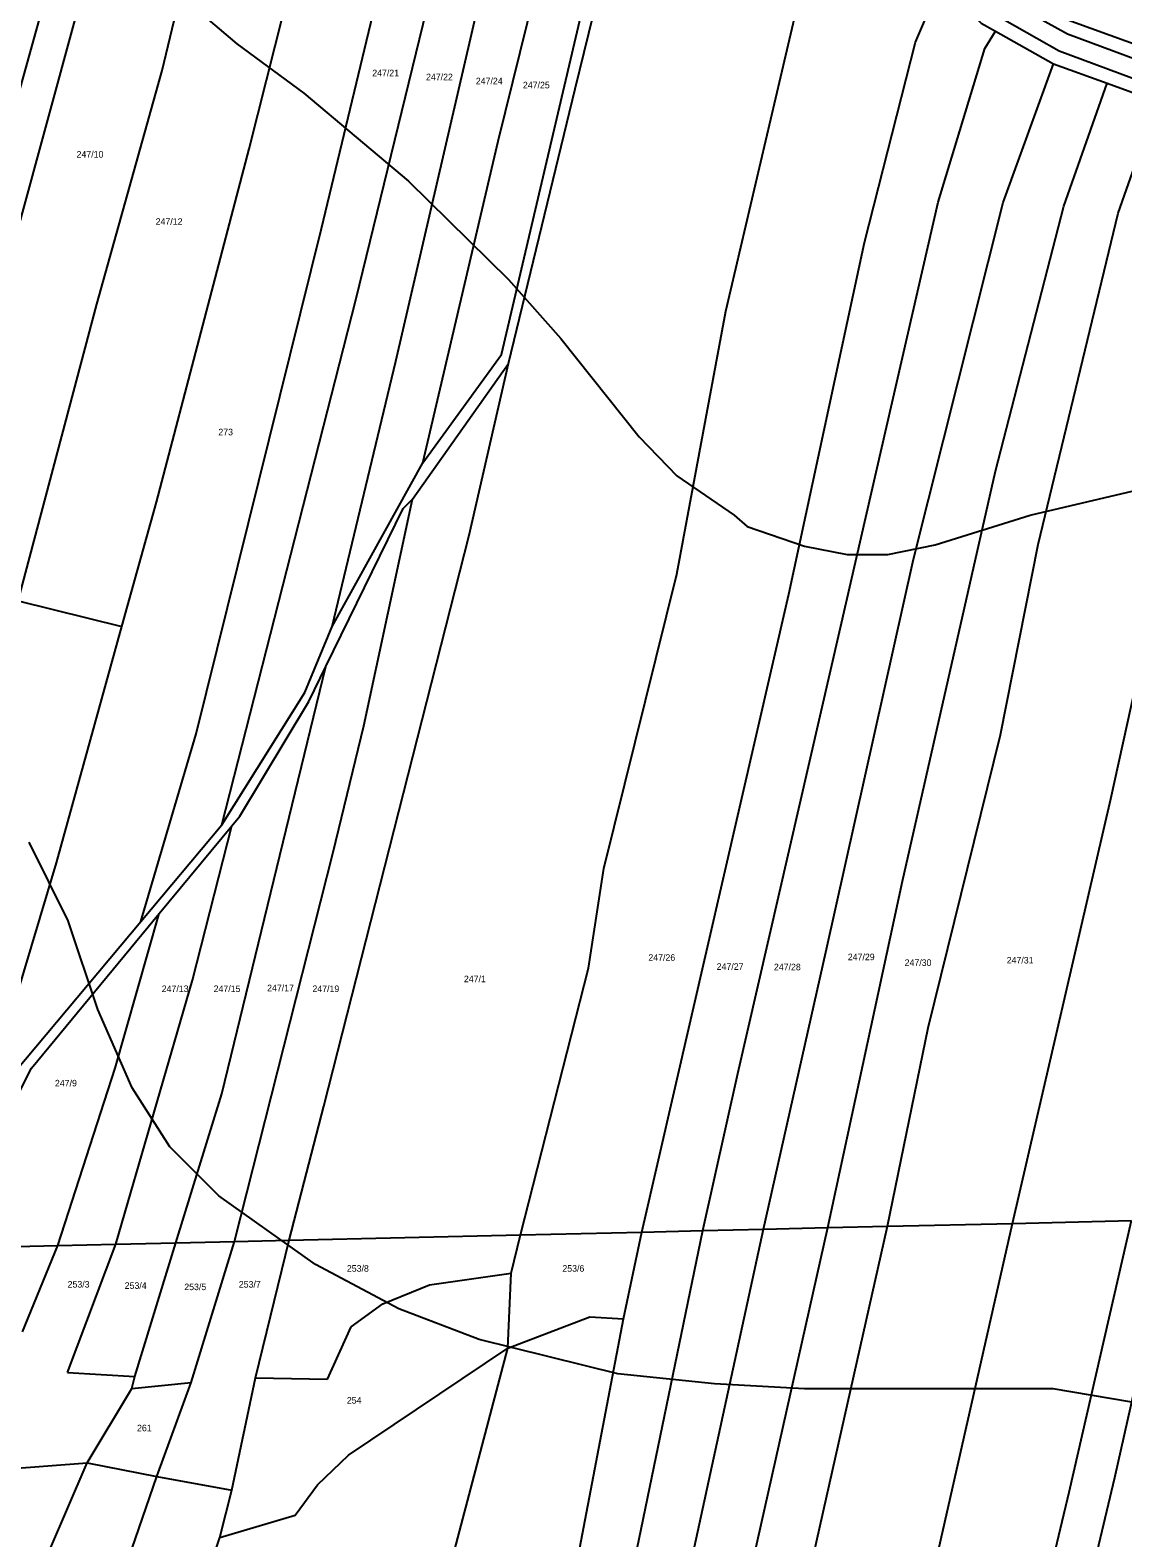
# Model space of a CAD drawing. Extents: x -743888 to -742027, y -1128394 to -1126768.
# Drawn here: x -743261.6 to -742978.3, y -1128180.2 to -1127789.2 of the extents above; entities that cross this region are included whole.
import ezdxf

# ---------------------------------------------------------------- set-up
doc = ezdxf.new("R2010")
doc.units = 0
for name, color, linetype in [('Vrstva 1', 7, 'Continuous'), ('Vrstva 18', 7, 'Continuous'), ('Vrstva 4', 7, 'Continuous'), ('Vrstva 52', 7, 'Continuous'), ('Vrstva 6', 7, 'Continuous')]:
    doc.layers.add(name, color=color, linetype=linetype)

msp = doc.modelspace()

# ---------------------------------------------------------------- linework, layer by layer
at = {"layer": 'Vrstva 1'}
for points in [[(-743015.05, -1127787.39), (-743011.33, -1127789.48)], [(-742991.64, -1127786.82), (-742967.48, -1127795.61)], [(-743011.33, -1127789.48), (-742996.28, -1127797.93)], [(-742996.28, -1127797.93), (-742982.41, -1127802.98)], [(-742982.41, -1127802.98), (-742971.25, -1127807.04)], [(-743134.48, -1128101.6), (-743103, -1128100.87)], [(-743103, -1128100.87), (-743087.22, -1128100.5)], [(-743087.22, -1128100.5), (-743071.48, -1128100.13)], [(-743071.48, -1128100.13), (-743054.77, -1128099.74)], [(-743054.77, -1128099.74), (-743039.34, -1128099.38)], [(-743039.34, -1128099.38), (-743006.9, -1128098.63)], [(-743006.9, -1128098.63), (-742976.11, -1128097.91)], [(-743283.67, -1128105.07), (-743254.5, -1128104.39)], [(-743254.5, -1128104.39), (-743239.47, -1128104.04)], [(-743239.47, -1128104.04), (-743223.91, -1128103.68)], [(-743223.91, -1128103.68), (-743208.7, -1128103.33)], [(-743208.7, -1128103.33), (-743194.5, -1128103)], [(-743194.5, -1128103), (-743134.48, -1128101.6)]]:
    msp.add_lwpolyline(points, dxfattribs=at)
at = {"layer": 'Vrstva 4'}
for points in [[(-743008.52, -1127781.37), (-742992.69, -1127790.12)], [(-743012.17, -1127784.72), (-742994.83, -1127794.53)], [(-742992.69, -1127790.12), (-742968.49, -1127799.16)], [(-742994.83, -1127794.53), (-742969.96, -1127803.78)]]:
    msp.add_lwpolyline(points, dxfattribs=at)
at = {"layer": 'Vrstva 52'}
for points in [[(-743053.67, -1127722.32), (-743053.72, -1127722.94), (-743049.21, -1127739.41), (-743048.14, -1127743.3), (-743040.35, -1127758.3), (-743030.5, -1127771.33), (-743025.38, -1127776.65), (-743015.05, -1127787.39), (-743011.33, -1127789.48), (-742996.28, -1127797.93), (-742982.41, -1127802.98), (-742971.25, -1127807.04), (-742969.31, -1127807.66), (-742941.27, -1127816.58), (-742913.36, -1127825.45), (-742905.98, -1127827.8), (-742901.58, -1127829.29), (-742887.63, -1127833.99), (-742883.39, -1127836.13), (-742870.31, -1127842.73), (-742866.75, -1127845.26), (-742862.04, -1127848.59)], [(-743039.23, -1127734.18), (-743037.36, -1127739.74), (-743036.47, -1127741.45), (-743030.16, -1127753.57), (-743021.89, -1127765.25), (-743006.65, -1127779.24), (-742997.92, -1127784.13), (-742991.64, -1127786.82), (-742967.48, -1127795.61), (-742902.77, -1127815.89), (-742889.66, -1127821.18), (-742882.56, -1127824.07), (-742864.61, -1127832.85), (-742855.17, -1127839.32)], [(-743237.75, -1127767.38), (-743208.06, -1127792.75), (-743190.69, -1127805.5), (-743163.5, -1127828.38), (-743137.63, -1127853.88), (-743124.06, -1127869.13), (-743103.69, -1127894.63), (-743093.94, -1127904.75), (-743079.13, -1127915), (-743075.69, -1127917.88), (-743060.88, -1127923), (-743049.81, -1127925.13), (-743039.25, -1127925.13), (-743026.94, -1127922.63), (-743002.31, -1127915), (-742975.56, -1127908.63)], [(-742971.38, -1128145.75), (-742996.38, -1128141.5), (-743060.88, -1128141.5), (-743084.19, -1128140.25), (-743109.25, -1128137.63), (-743145.25, -1128128.75), (-743166.06, -1128120.75), (-743187.69, -1128109.25), (-743212.75, -1128091.5), (-743225.44, -1128078.75), (-743235.19, -1128063.5), (-743244.13, -1128043.13), (-743251.75, -1128020.13), (-743261.94, -1127999.75)]]:
    msp.add_lwpolyline(points, dxfattribs=at)
at = {"layer": 'Vrstva 6'}
for points in [[(-743227.42, -1127799.64), (-743205.44, -1127708.1)], [(-743186.13, -1127840.64), (-743155.72, -1127714.23)], [(-743140.31, -1127817.95), (-743115.61, -1127717.91)], [(-743166.85, -1127875.07), (-743131.1, -1127720.81)], [(-743120.32, -1127804.45), (-743100.45, -1127723.29)], [(-743204.89, -1127820), (-743186.75, -1127748.28)], [(-743300.05, -1127932.95), (-743249, -1127749.54)], [(-743177.21, -1127859.16), (-743152.4, -1127757.44)], [(-743139.42, -1127873.34), (-743112.61, -1127758.91)], [(-743081.3, -1127862.06), (-743057.88, -1127762.39)], [(-743032.09, -1127792.31), (-743025.38, -1127776.65)], [(-743287.33, -1127923.2), (-743249.75, -1127785.46)], [(-743045.29, -1127844.24), (-743032.09, -1127792.31)], [(-743014.07, -1127793.96), (-743011.33, -1127789.48)], [(-743026.17, -1127833.83), (-743014.07, -1127793.96)], [(-743244.37, -1127860.25), (-743227.42, -1127799.64)], [(-743009.32, -1127833.88), (-742996.28, -1127797.93)], [(-742993.62, -1127834.86), (-742982.41, -1127802.98)], [(-743137.57, -1127875.6), (-743120.32, -1127804.45)], [(-742979.49, -1127836.62), (-742969.31, -1127807.66)], [(-743159.84, -1127901.41), (-743140.31, -1127817.95)], [(-743228.87, -1127911.59), (-743204.89, -1127820)], [(-743051.52, -1127944.14), (-743026.17, -1127833.83)], [(-743032.57, -1127926.34), (-743009.32, -1127833.88)], [(-743011.3, -1127903.56), (-742993.62, -1127834.86)], [(-743000.24, -1127922.55), (-742979.49, -1127836.62)], [(-743218.63, -1127971.66), (-743186.13, -1127840.64)], [(-743064.96, -1127935.44), (-743045.29, -1127844.24)], [(-743264.74, -1127937.21), (-743244.37, -1127860.25)], [(-743211.94, -1127995.24), (-743177.21, -1127859.16)], [(-743093.99, -1127930.3), (-743081.3, -1127862.06)], [(-742981.41, -1127988.5), (-742954.92, -1127868.05)], [(-743159.84, -1127901.41), (-743139.42, -1127873.34)], [(-743183.31, -1127943.86), (-743166.85, -1127875.07)], [(-743162.47, -1127910.78), (-743137.57, -1127875.6)], [(-743147.81, -1127920.19), (-743137.57, -1127875.6)], [(-743183.31, -1127943.86), (-743159.84, -1127901.41)], [(-743035.44, -1128009.87), (-743011.3, -1127903.56)], [(-743237.87, -1127943.87), (-743228.87, -1127911.59)], [(-743184.94, -1127954.19), (-743164.89, -1127913.26)], [(-743175.1, -1127969.59), (-743162.47, -1127910.78)], [(-743164.89, -1127913.26), (-743162.47, -1127910.78)], [(-743185.51, -1128068.25), (-743147.81, -1127920.19)], [(-743010.01, -1127971.9), (-743000.24, -1127922.55)], [(-743055.35, -1128028.26), (-743032.57, -1127926.34)], [(-743112.87, -1128006.6), (-743093.99, -1127930.3)], [(-743103, -1128100.87), (-743064.96, -1127935.44)], [(-743264.74, -1127937.21), (-743237.87, -1127943.87)], [(-743254.82, -1128005.17), (-743237.87, -1127943.87)], [(-743190.45, -1127960.97), (-743183.31, -1127943.86)], [(-743078.12, -1128059.75), (-743051.52, -1127944.14)], [(-743211.98, -1128065), (-743184.94, -1127954.19)], [(-743189.39, -1127963.29), (-743184.94, -1127954.19)], [(-743211.94, -1127995.24), (-743190.45, -1127960.97)], [(-743207.28, -1127993.05), (-743189.39, -1127963.29)], [(-743232.97, -1128020.31), (-743218.63, -1127971.66)], [(-743183.09, -1128002.36), (-743175.1, -1127969.59)], [(-743028.83, -1128047.9), (-743010.01, -1127971.9)], [(-743006.9, -1128098.63), (-742981.41, -1127988.5)], [(-743232.97, -1128020.31), (-743211.94, -1127995.24)], [(-743228.15, -1128018.27), (-743209.35, -1127995.55)], [(-743219.54, -1128035.53), (-743209.35, -1127995.55)], [(-743209.35, -1127995.55), (-743207.28, -1127993.05)], [(-743208.7, -1128103.33), (-743183.09, -1128002.36)], [(-743274.12, -1128069.36), (-743254.82, -1128005.17)], [(-743116.84, -1128032.47), (-743112.87, -1128006.6)], [(-743054.77, -1128099.74), (-743035.44, -1128009.87)], [(-743261.3, -1128058.36), (-743228.15, -1128018.27)], [(-743239.6, -1128058.4), (-743228.15, -1128018.27)], [(-743274.12, -1128069.36), (-743232.97, -1128020.31)], [(-743071.48, -1128100.13), (-743055.35, -1128028.26)], [(-743134.48, -1128101.6), (-743116.84, -1128032.47)], [(-743239.47, -1128104.04), (-743219.54, -1128035.53)], [(-743039.34, -1128099.38), (-743028.83, -1128047.9)], [(-743286.03, -1128107.53), (-743261.3, -1128058.36)], [(-743254.5, -1128104.39), (-743239.6, -1128058.4)], [(-743087.22, -1128100.5), (-743078.12, -1128059.75)], [(-743223.91, -1128103.68), (-743211.98, -1128065)], [(-743194.5, -1128103), (-743185.51, -1128068.25)], [(-743107.8, -1128123.39), (-743103, -1128100.87)], [(-743106.46, -1128193.81), (-743087.22, -1128100.5)], [(-743093.13, -1128199.64), (-743071.48, -1128100.13)], [(-743083.7, -1128228.32), (-743054.77, -1128099.74)], [(-743064.75, -1128212.33), (-743039.34, -1128099.38)], [(-743035.53, -1128224.97), (-743006.9, -1128098.63)], [(-742992.2, -1128168.37), (-742976.11, -1128097.91)], [(-742980.43, -1128164.49), (-742965.39, -1128097.66)], [(-743263.65, -1128126.74), (-743254.5, -1128104.39)], [(-743251.93, -1128137.29), (-743239.47, -1128104.04)], [(-743234.48, -1128138.33), (-743223.91, -1128103.68)], [(-743219.88, -1128139.9), (-743208.7, -1128103.33)], [(-743203.2, -1128138.64), (-743194.5, -1128103)], [(-743136.91, -1128111.57), (-743134.48, -1128101.6)], [(-743158.1, -1128114.53), (-743136.91, -1128111.57)], [(-743137.82, -1128130.98), (-743136.91, -1128111.57)], [(-743170.21, -1128119.49), (-743158.1, -1128114.53)], [(-743178.41, -1128125.48), (-743170.21, -1128119.49)], [(-743137.82, -1128130.98), (-743116.53, -1128122.87)], [(-743122.33, -1128199.54), (-743107.8, -1128123.39)], [(-743116.53, -1128122.87), (-743107.8, -1128123.39)], [(-743184.58, -1128139.03), (-743178.41, -1128125.48)], [(-743179.11, -1128158.7), (-743137.82, -1128130.98)], [(-743169.9, -1128252.98), (-743137.82, -1128130.98)], [(-743251.93, -1128137.29), (-743234.48, -1128138.33)], [(-743235.27, -1128141.46), (-743234.48, -1128138.33)], [(-743235.27, -1128141.46), (-743219.88, -1128139.9)], [(-743228.78, -1128164.26), (-743219.88, -1128139.9)], [(-743209.31, -1128167.82), (-743203.2, -1128138.64)], [(-743203.2, -1128138.64), (-743184.58, -1128139.03)], [(-743246.85, -1128160.74), (-743235.27, -1128141.46)], [(-743187.18, -1128166.39), (-743179.11, -1128158.7)], [(-743267.29, -1128162.3), (-743246.85, -1128160.74)], [(-743261.61, -1128195.12), (-743246.85, -1128160.74)], [(-743246.85, -1128160.74), (-743228.78, -1128164.26)], [(-743241.7, -1128201.74), (-743228.78, -1128164.26)], [(-743228.78, -1128164.26), (-743209.31, -1128167.82)], [(-743192.91, -1128174.33), (-743187.18, -1128166.39)], [(-743011.02, -1128293.29), (-742980.43, -1128164.49)], [(-743212.44, -1128180.07), (-743209.31, -1128167.82)], [(-742998.95, -1128196.62), (-742992.2, -1128168.37)], [(-743212.44, -1128180.07), (-743192.91, -1128174.33)], [(-743236.49, -1128253.2), (-743212.44, -1128180.07)]]:
    msp.add_lwpolyline(points, dxfattribs=at)

# ---------------------------------------------------------------- texts
at = {"layer": 'Vrstva 18'}
for s, p in [('247/21', (-743172.94, -1127801.14)), ('247/22', (-743158.99, -1127802.18)), ('247/24', (-743146.08, -1127803.23)), ('247/25', (-743133.87, -1127804.28)), ('247/10', (-743249.61, -1127822.25)), ('247/12', (-743229.1, -1127839.67)), ('273', (-743212.85, -1127894.26)), ('247/26', (-743101.34, -1128030.53)), ('247/29', (-743049.62, -1128030.37)), ('247/30', (-743034.89, -1128031.87)), ('247/31', (-743008.42, -1128031.23)), ('247/1', (-743149.17, -1128036.08)), ('247/27', (-743083.62, -1128032.88)), ('247/28', (-743068.78, -1128032.99)), ('247/13', (-743227.53, -1128038.64)), ('247/15', (-743214.07, -1128038.64)), ('247/17', (-743200.2, -1128038.43)), ('247/19', (-743188.45, -1128038.64)), ('247/9', (-743255.22, -1128063.11)), ('253/8', (-743179.52, -1128111.16)), ('253/6', (-743123.64, -1128111.16)), ('253/3', (-743251.93, -1128115.28)), ('253/4', (-743237.13, -1128115.61)), ('253/5', (-743221.68, -1128115.94)), ('253/7', (-743207.54, -1128115.28)), ('254', (-743179.52, -1128145.37)), ('261', (-743233.93, -1128152.54))]:
    msp.add_text(s, height=1.7, dxfattribs=at).set_placement(p)

doc.saveas('drawing.dxf')
